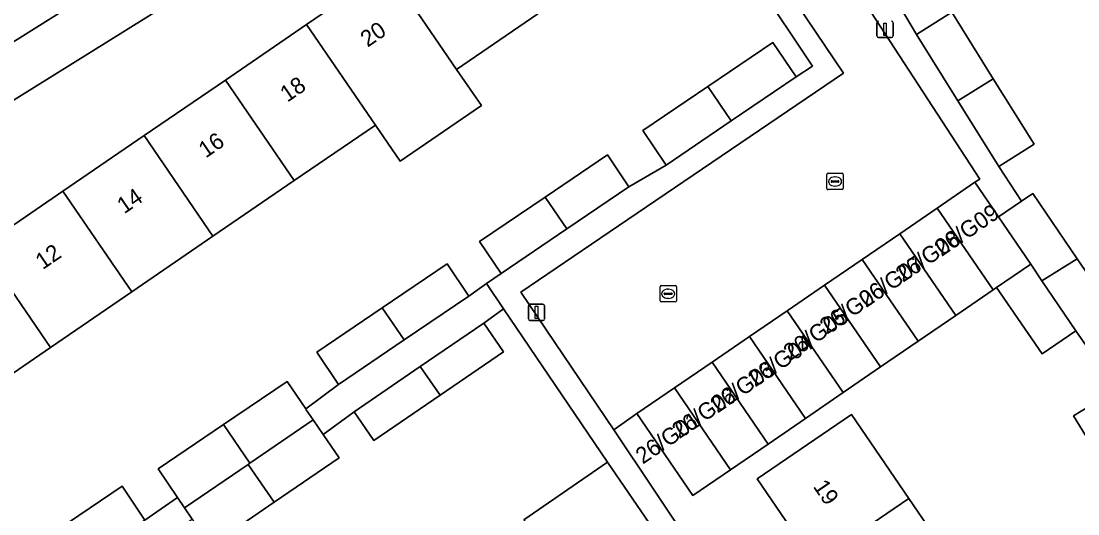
# Model space of a CAD drawing. Extents: x 160030 to 160839, y 385325 to 386450.
# Drawn here: x 160124.4 to 160188.9, y 386051.6 to 386081.7 of the extents above; entities that cross this region are included whole.
import ezdxf

# ---------------------------------------------------------------- set-up
doc = ezdxf.new("R2010")
doc.units = 0
for name, color, linetype in [('IMGEO_Erf', 7, 'Continuous'), ('IMGEO_Kolk', 7, 'Continuous'), ('IMGEO_Lichtmast', 7, 'Continuous'), ('IMGEO_Pand', 7, 'Continuous'), ('IMGEO_Pand_nummerreeks', 7, 'Continuous'), ('IMGEO_Rijbaan_lokaal_open', 7, 'Continuous'), ('IMGEO_Voetpad_open', 7, 'Continuous')]:
    doc.layers.add(name, color=color, linetype=linetype)

msp = doc.modelspace()

# ---------------------------------------------------------------- linework, layer by layer
at = {"layer": 'IMGEO_Erf'}
for points in [[(160183.28, 386113.595), (160165.486, 386102.698), (160168.832, 386097.411), (160170.981, 386098.751), (160173.566, 386094.606), (160171.417, 386093.265), (160172.7, 386091.137), (160174.829, 386092.465), (160177.447, 386088.267), (160179.927, 386084.289), (160177.799, 386082.962), (160179.047, 386080.859), (160181.207, 386082.206), (160183.737, 386078.148), (160186.229, 386074.152), (160184.069, 386072.805), (160185.453, 386070.676), (160186.141, 386071.147), (160188.863, 386067.169), (160191.665, 386063.073)], [(160159.187, 386098.82), (160091.182, 386056.49)], [(160146.42, 386064.171), (160150.384, 386066.856), (160151.713, 386064.894), (160152.79, 386065.648), (160153.684, 386066.274), (160152.371, 386068.212), (160156.367, 386070.918), (160160.18, 386073.501), (160161.492, 386071.565), (160163.758, 386072.888), (160162.334, 386074.992), (160166.304, 386077.681), (160170.272, 386080.369), (160171.697, 386078.265), (160172.704, 386078.926), (160165.988, 386088.991)], [(160121.97, 386067.895), (160126.931, 386071.288), (160131.891, 386074.682), (160136.851, 386078.074), (160141.812, 386081.467), (160146.773, 386084.861)], [(160155.932, 386082.113), (160150.972, 386078.72), (160152.483, 386076.51), (160147.523, 386073.119), (160146.012, 386075.327), (160141.051, 386071.933), (160136.092, 386068.541), (160131.131, 386065.148), (160126.17, 386061.754), (160121.209, 386058.361)], [(160189.561, 386061.634), (160188.783, 386062.773), (160186.714, 386061.358), (160183.941, 386065.411), (160183.731, 386065.267), (160181.439, 386063.7), (160179.147, 386062.132), (160176.856, 386060.565), (160174.564, 386058.997), (160172.272, 386057.43), (160169.981, 386055.862), (160167.689, 386054.295), (160165.397, 386052.727), (160161.98, 386057.723), (160160.565, 386056.736), (160167.958, 386045.687), (160168.74, 386046.216), (160193.278, 386010.244)], [(160090.259, 386052.141), (160103.879, 386032.138), (160107.902, 386034.877), (160106.518, 386036.9), (160110.632, 386039.714), (160112.016, 386037.691), (160113.966, 386039.191), (160112.666, 386041.11), (160116.657, 386043.813), (160120.621, 386046.498), (160121.915, 386044.589), (160123.992, 386045.822), (160122.587, 386047.896), (160126.575, 386050.597), (160130.542, 386053.284), (160131.941, 386051.219), (160133.921, 386052.599), (160132.739, 386054.344), (160136.731, 386057.047), (160140.616, 386059.678), (160141.757, 386058.009), (160143.764, 386059.497), (160142.429, 386061.468), (160146.42, 386064.171)], [(160155.067, 386051.243), (160160.19, 386054.748), (160153.833, 386064.11), (160152.622, 386063.238), (160153.824, 386061.481), (160149.963, 386058.84), (160145.923, 386056.076), (160144.72, 386057.834), (160142.827, 386056.445), (160143.799, 386055.023), (160139.829, 386052.308), (160135.926, 386049.639)], [(160191.02, 386053.691), (160188.632, 386057.573), (160190.967, 386059.01)]]:
    msp.add_lwpolyline(points, dxfattribs=at)
msp.add_lwpolyline([(160181.966, 386047.596), (160185.353, 386042.644), (160188.638, 386037.843), (160190.97, 386039.438), (160194.4, 386034.422), (160192.068, 386032.827), (160192.128, 386032.739), (160195.516, 386027.788), (160198.903, 386022.835), (160202.403, 386017.719), (160196.655, 386013.786), (160193.155, 386018.903), (160189.767, 386023.856), (160186.38, 386028.807), (160182.992, 386033.76), (160179.604, 386038.712), (160176.217, 386043.664), (160172.829, 386048.617), (160169.329, 386053.734), (160175.077, 386057.667), (160178.578, 386052.548)], close=True, dxfattribs=at)
at = {"layer": 'IMGEO_Kolk'}
for p, q in [((160173.573, 386071.457), (160173.573, 386072.309)), ((160173.648, 386072.383), (160174.5, 386072.383)), ((160174.061, 386072.163), (160174.086, 386072.163)), ((160174.574, 386072.309), (160174.574, 386071.457)), ((160173.832, 386071.877), (160173.832, 386071.889)), ((160174.27, 386071.84), (160173.872, 386071.84)), ((160173.875, 386071.926), (160174.273, 386071.926)), ((160174.084, 386071.603), (160174.059, 386071.603)), ((160174.316, 386071.889), (160174.316, 386071.877)), ((160174.5, 386071.383), (160173.648, 386071.383)), ((160163.387, 386064.606), (160163.387, 386065.458)), ((160163.462, 386065.532), (160164.314, 386065.532)), ((160163.646, 386065.026), (160163.646, 386065.038)), ((160163.689, 386065.075), (160164.087, 386065.075)), ((160163.875, 386065.312), (160163.9, 386065.312)), ((160164.13, 386065.038), (160164.13, 386065.026)), ((160164.388, 386065.458), (160164.388, 386064.606)), ((160164.314, 386064.532), (160163.462, 386064.532)), ((160164.084, 386064.989), (160163.686, 386064.989)), ((160163.898, 386064.752), (160163.873, 386064.752))]:
    msp.add_line(p, q, dxfattribs=at)
for points in [[(160173.573, 386071.457), (160173.573, 386072.309)], [(160173.648, 386072.383), (160174.5, 386072.383)], [(160174.574, 386072.309), (160174.574, 386071.457)], [(160174.5, 386071.383), (160173.648, 386071.383)], [(160163.387, 386064.606), (160163.387, 386065.458)], [(160163.462, 386065.532), (160164.314, 386065.532)], [(160164.388, 386065.458), (160164.388, 386064.606)], [(160164.314, 386064.532), (160163.462, 386064.532)]]:
    msp.add_lwpolyline(points, dxfattribs=at)
for centre, radius, start, end in [((160173.65, 386072.307), 0.0765, 91.55205, 178.44795), ((160173.65, 386072.307), 0.0765, 91.55205, 178.44795), ((160174.498, 386072.307), 0.0765, 1.55205, 88.44795), ((160174.498, 386072.307), 0.0765, 1.55205, 88.44795), ((160173.872, 386071.886), 0.0403, 85.87752, 175.75265), ((160173.869, 386071.876), 0.0366, 178.93798, 274.71019), ((160174.273, 386071.883), 0.043, 264.86636, 352.45326), ((160174.277, 386071.888), 0.0386, 1.73085, 96.63898), ((160173.65, 386071.459), 0.0765, 181.55205, 268.44795), ((160173.65, 386071.459), 0.0765, 181.55205, 268.44795), ((160174.498, 386071.459), 0.0765, 271.55205, 358.44795), ((160174.498, 386071.459), 0.0765, 271.55205, 358.44795), ((160163.464, 386065.456), 0.0765, 91.55205, 178.44795), ((160163.464, 386065.456), 0.0765, 91.55205, 178.44795), ((160163.686, 386065.035), 0.0403, 85.87752, 175.75265), ((160163.683, 386065.025), 0.0366, 178.93798, 274.71019), ((160164.087, 386065.032), 0.043, 264.86636, 352.45326), ((160164.091, 386065.037), 0.0386, 1.73085, 96.63898), ((160164.312, 386065.456), 0.0765, 1.55205, 88.44795), ((160164.312, 386065.456), 0.0765, 1.55205, 88.44795), ((160163.464, 386064.608), 0.0765, 181.55205, 268.44795), ((160163.464, 386064.608), 0.0765, 181.55205, 268.44795), ((160164.312, 386064.608), 0.0765, 271.55205, 358.44795), ((160164.312, 386064.608), 0.0765, 271.55205, 358.44795)]:
    msp.add_arc(centre, radius, start, end, dxfattribs=at)
for centre, major_axis, ratio, start_param, end_param in [((160174.06, 386071.883), (-0.387, 0.002), 0.722429, 4.712389, 7.853982), ((160174.085, 386071.883), (-0.39, 0.002), 0.717154, 1.570796, 4.712389), ((160163.874, 386065.032), (-0.387, 0.002), 0.722429, 4.712389, 7.853982), ((160163.899, 386065.032), (-0.39, 0.002), 0.717154, 1.570796, 4.712389)]:
    msp.add_ellipse(centre, major_axis=major_axis, ratio=ratio, start_param=start_param, end_param=end_param, dxfattribs=at)
at = {"layer": 'IMGEO_Lichtmast'}
for p, q in [((160176.628, 386080.766), (160176.628, 386081.566)), ((160176.628, 386081.566), (160176.628, 386080.766)), ((160177.618, 386081.566), (160177.618, 386080.766)), ((160177.618, 386080.766), (160177.618, 386081.566)), ((160177.518, 386080.666), (160176.728, 386080.666)), ((160176.728, 386080.666), (160177.518, 386080.666)), ((160155.448, 386064.393), (160156.238, 386064.393)), ((160156.238, 386064.393), (160155.448, 386064.393)), ((160155.348, 386063.493), (160155.348, 386064.293)), ((160155.348, 386064.293), (160155.348, 386063.493)), ((160156.338, 386064.293), (160156.338, 386063.493)), ((160156.338, 386063.493), (160156.338, 386064.293)), ((160156.238, 386063.393), (160155.448, 386063.393)), ((160155.448, 386063.393), (160156.238, 386063.393))]:
    msp.add_line(p, q, dxfattribs=at)
for points in [[(160177.048, 386081.541), (160177.198, 386081.541), (160177.198, 386080.791), (160177.048, 386080.791), (160177.048, 386081.541)], [(160155.768, 386064.268), (160155.918, 386064.268), (160155.918, 386063.518), (160155.768, 386063.518), (160155.768, 386064.268)]]:
    msp.add_lwpolyline(points, dxfattribs=at)
for centre, start, end in [((160176.728, 386081.566), 90, 180), ((160176.728, 386081.566), 90, 180), ((160177.518, 386081.566), 0, 90), ((160177.518, 386081.566), 360, 90), ((160176.728, 386080.766), 180, 270), ((160176.728, 386080.766), 180, 270), ((160177.518, 386080.766), 270, 0), ((160177.518, 386080.766), 270, 0), ((160155.448, 386064.293), 90, 180), ((160155.448, 386064.293), 90, 180), ((160156.238, 386064.293), 0, 90), ((160156.238, 386064.293), 360, 90), ((160155.448, 386063.493), 180, 270), ((160155.448, 386063.493), 180, 270), ((160156.238, 386063.493), 270, 0), ((160156.238, 386063.493), 270, 0)]:
    msp.add_arc(centre, 0.1, start, end, dxfattribs=at)
at = {"layer": 'IMGEO_Pand'}
for points in [[(160151.733, 386088.254), (160146.773, 386084.861), (160150.972, 386078.72), (160155.932, 386082.113)], [(160146.773, 386084.861), (160141.812, 386081.467), (160146.012, 386075.327), (160147.523, 386073.119), (160152.483, 386076.51), (160150.972, 386078.72)], [(160183.737, 386078.148), (160181.207, 386082.206), (160179.047, 386080.859), (160181.572, 386076.81)], [(160141.051, 386071.933), (160146.012, 386075.327), (160141.812, 386081.467), (160136.851, 386078.074)], [(160167.74, 386075.585), (160171.697, 386078.265), (160170.272, 386080.369), (160166.304, 386077.681)], [(160136.092, 386068.541), (160141.051, 386071.933), (160136.851, 386078.074), (160131.891, 386074.682)], [(160181.572, 386076.81), (160184.069, 386072.805), (160186.229, 386074.152), (160183.737, 386078.148)], [(160166.304, 386077.681), (160162.334, 386074.992), (160163.758, 386072.888), (160167.74, 386075.585)], [(160131.891, 386074.682), (160126.931, 386071.288), (160131.131, 386065.148), (160136.092, 386068.541)], [(160161.492, 386071.565), (160160.18, 386073.501), (160156.367, 386070.918), (160157.689, 386068.988)], [(160183.941, 386065.411), (160186.022, 386066.835), (160184.051, 386069.717), (160182.605, 386071.831), (160180.313, 386070.263), (160183.731, 386065.267)], [(160126.17, 386061.754), (160131.131, 386065.148), (160126.931, 386071.288), (160121.97, 386067.895)], [(160157.689, 386068.988), (160156.367, 386070.918), (160152.371, 386068.212), (160153.684, 386066.274)], [(160184.051, 386069.717), (160186.022, 386066.835), (160186.7, 386065.822), (160188.863, 386067.169), (160186.141, 386071.147), (160185.453, 386070.676)], [(160181.439, 386063.7), (160183.731, 386065.267), (160180.313, 386070.263), (160178.022, 386068.696)], [(160178.022, 386068.696), (160175.73, 386067.128), (160179.147, 386062.132), (160181.439, 386063.7)], [(160121.97, 386067.895), (160117.009, 386064.502), (160121.209, 386058.361), (160126.17, 386061.754)], [(160176.856, 386060.565), (160179.147, 386062.132), (160175.73, 386067.128), (160173.438, 386065.561)], [(160188.863, 386067.169), (160186.7, 386065.822), (160188.783, 386062.773), (160189.561, 386061.634), (160190.502, 386062.278), (160191.665, 386063.073)], [(160151.713, 386064.894), (160150.384, 386066.856), (160146.42, 386064.171), (160147.762, 386062.212)], [(160186.7, 386065.822), (160186.022, 386066.835), (160183.941, 386065.411), (160186.714, 386061.358), (160188.783, 386062.773)], [(160174.564, 386058.997), (160176.856, 386060.565), (160173.438, 386065.561), (160171.147, 386063.993)], [(160147.762, 386062.212), (160146.42, 386064.171), (160142.429, 386061.468), (160143.764, 386059.497)], [(160172.272, 386057.43), (160174.564, 386058.997), (160171.147, 386063.993), (160168.855, 386062.426)], [(160152.622, 386063.238), (160148.753, 386060.592), (160149.963, 386058.84), (160153.824, 386061.481)], [(160168.855, 386062.426), (160166.563, 386060.858), (160169.981, 386055.862), (160172.272, 386057.43)], [(160149.963, 386058.84), (160148.753, 386060.592), (160144.72, 386057.834), (160145.923, 386056.076)], [(160167.689, 386054.295), (160169.981, 386055.862), (160166.563, 386060.858), (160164.272, 386059.291)], [(160141.757, 386058.009), (160140.616, 386059.678), (160136.731, 386057.047), (160138.345, 386054.69), (160142.216, 386057.338), (160141.792, 386057.958)], [(160161.98, 386057.723), (160165.397, 386052.727), (160167.689, 386054.295), (160164.272, 386059.291)], [(160193.296, 386055.223), (160190.967, 386059.01), (160188.632, 386057.573), (160191.02, 386053.691)], [(160142.827, 386056.445), (160142.216, 386057.338), (160138.345, 386054.69), (160138.244, 386054.621), (160139.829, 386052.308), (160143.799, 386055.023)], [(160178.578, 386052.548), (160175.077, 386057.667), (160169.329, 386053.734), (160172.829, 386048.617)], [(160136.731, 386057.047), (160132.739, 386054.344), (160133.921, 386052.599), (160134.353, 386051.961), (160138.244, 386054.621), (160138.345, 386054.69)], [(160158.904, 386045.635), (160164.027, 386049.139), (160160.19, 386054.748), (160155.067, 386051.243)], [(160139.829, 386052.308), (160138.244, 386054.621), (160134.353, 386051.961), (160134.822, 386051.268), (160135.926, 386049.639)], [(160127.989, 386048.536), (160131.941, 386051.219), (160130.542, 386053.284), (160126.575, 386050.597)], [(160181.966, 386047.596), (160178.578, 386052.548), (160172.829, 386048.617), (160176.217, 386043.664)]]:
    msp.add_lwpolyline(points, close=True, dxfattribs=at)
at = {"layer": 'IMGEO_Rijbaan_lokaal_open'}
msp.add_lwpolyline([(160087.323, 386057.846), (160094.533, 386062.106), (160099.153, 386064.979), (160118.044, 386076.749), (160139.704, 386090.325), (160150.065, 386096.702), (160157.055, 386101.145), (160160.784, 386103.485), (160163.896, 386105.423), (160181.465, 386116.274)], dxfattribs=at)
msp.add_lwpolyline([(160178.022, 386068.696), (160180.313, 386070.263), (160182.605, 386071.831), (160182.92, 386072.031), (160174.551, 386084.875), (160166.941, 386097.434), (160164.187, 386101.902), (160160.445, 386099.596), (160164.248, 386093.899), (160169.515, 386086.023), (160174.582, 386078.498), (160160.285, 386068.789), (160154.885, 386065.127), (160160.565, 386056.736), (160161.98, 386057.723), (160164.272, 386059.291), (160166.563, 386060.858), (160168.855, 386062.426), (160171.147, 386063.993), (160173.438, 386065.561), (160175.73, 386067.128)], close=True, dxfattribs=at)
at = {"layer": 'IMGEO_Voetpad_open'}
for points in [[(160175.325, 386086.928), (160172.7, 386091.137), (160171.417, 386093.265), (160168.832, 386097.411), (160165.486, 386102.698), (160164.297, 386101.97), (160164.187, 386101.902), (160166.941, 386097.434), (160174.551, 386084.875), (160182.92, 386072.031), (160182.605, 386071.831), (160184.051, 386069.717), (160185.453, 386070.676), (160184.069, 386072.805), (160181.572, 386076.81), (160179.047, 386080.859), (160177.799, 386082.962)], [(160164.248, 386093.899), (160160.445, 386099.596), (160159.187, 386098.82), (160161.784, 386095.129), (160165.988, 386088.991), (160172.704, 386078.926), (160171.697, 386078.265), (160167.74, 386075.585), (160163.758, 386072.888), (160161.492, 386071.565), (160157.689, 386068.988), (160153.684, 386066.274), (160152.79, 386065.648), (160153.833, 386064.11), (160160.19, 386054.748), (160164.027, 386049.139), (160166.76, 386044.877), (160167.958, 386045.687), (160160.565, 386056.736), (160154.885, 386065.127), (160160.285, 386068.789), (160174.582, 386078.498), (160169.515, 386086.023)], [(160152.622, 386063.238), (160153.833, 386064.11), (160152.79, 386065.648), (160151.713, 386064.894), (160147.762, 386062.212), (160143.764, 386059.497), (160141.757, 386058.009), (160141.792, 386057.958), (160142.216, 386057.338), (160142.827, 386056.445), (160144.72, 386057.834), (160148.753, 386060.592)], [(160122.602, 386042.978), (160124.928, 386044.569), (160128.748, 386047.182), (160132.71, 386049.893), (160134.822, 386051.268), (160134.353, 386051.961), (160133.921, 386052.599), (160131.941, 386051.219), (160127.989, 386048.536), (160123.992, 386045.822), (160121.915, 386044.589), (160117.963, 386041.905), (160113.966, 386039.191), (160112.016, 386037.691), (160107.902, 386034.877), (160103.879, 386032.138), (160104.787, 386030.805), (160108.827, 386033.556), (160112.941, 386036.37), (160115.045, 386037.809), (160118.813, 386040.386)]]:
    msp.add_lwpolyline(points, close=True, dxfattribs=at)
for points in [[(160159.187, 386098.82), (160160.445, 386099.596), (160157.186, 386101.085), (160157.055, 386101.145), (160150.065, 386096.702), (160139.704, 386090.325), (160118.044, 386076.749), (160099.153, 386064.979), (160094.533, 386062.106), (160087.323, 386057.846), (160089.794, 386054.512)], [(160091.182, 386056.49), (160159.187, 386098.82)]]:
    msp.add_lwpolyline(points, dxfattribs=at)

# ---------------------------------------------------------------- texts
at = {"layer": 'IMGEO_Pand_nummerreeks'}
for s, rotation, p in [('20', 34.37174, (160145.535, 386080.041)), ('18', 34.37317, (160140.632, 386076.687)), ('16', 34.37317, (160135.653, 386073.281)), ('14', 34.37317, (160130.675, 386069.876)), ('26/G09', 34.33447, (160180.578, 386067.271)), ('26/G08', 34.33447, (160178.223, 386065.696)), ('12', 34.37317, (160125.695, 386066.47)), ('26/G07', 34.33447, (160175.966, 386064.149)), ('26/G06', 34.33447, (160173.581, 386062.525)), ('26/G05', 34.33447, (160171.363, 386060.934)), ('26/G04', 34.33447, (160169.2, 386059.306)), ('26/G03', 34.33447, (160166.899, 386057.716)), ('26/G02', 34.33447, (160164.563, 386056.151)), ('26/G01', 34.33447, (160162.336, 386054.601)), ('19', 304.37366, (160172.702, 386053.267))]:
    msp.add_text(s, height=1, rotation=rotation, dxfattribs=at).set_placement(p)

doc.saveas('drawing.dxf')
